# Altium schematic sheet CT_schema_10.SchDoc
size 405 x 220 mm
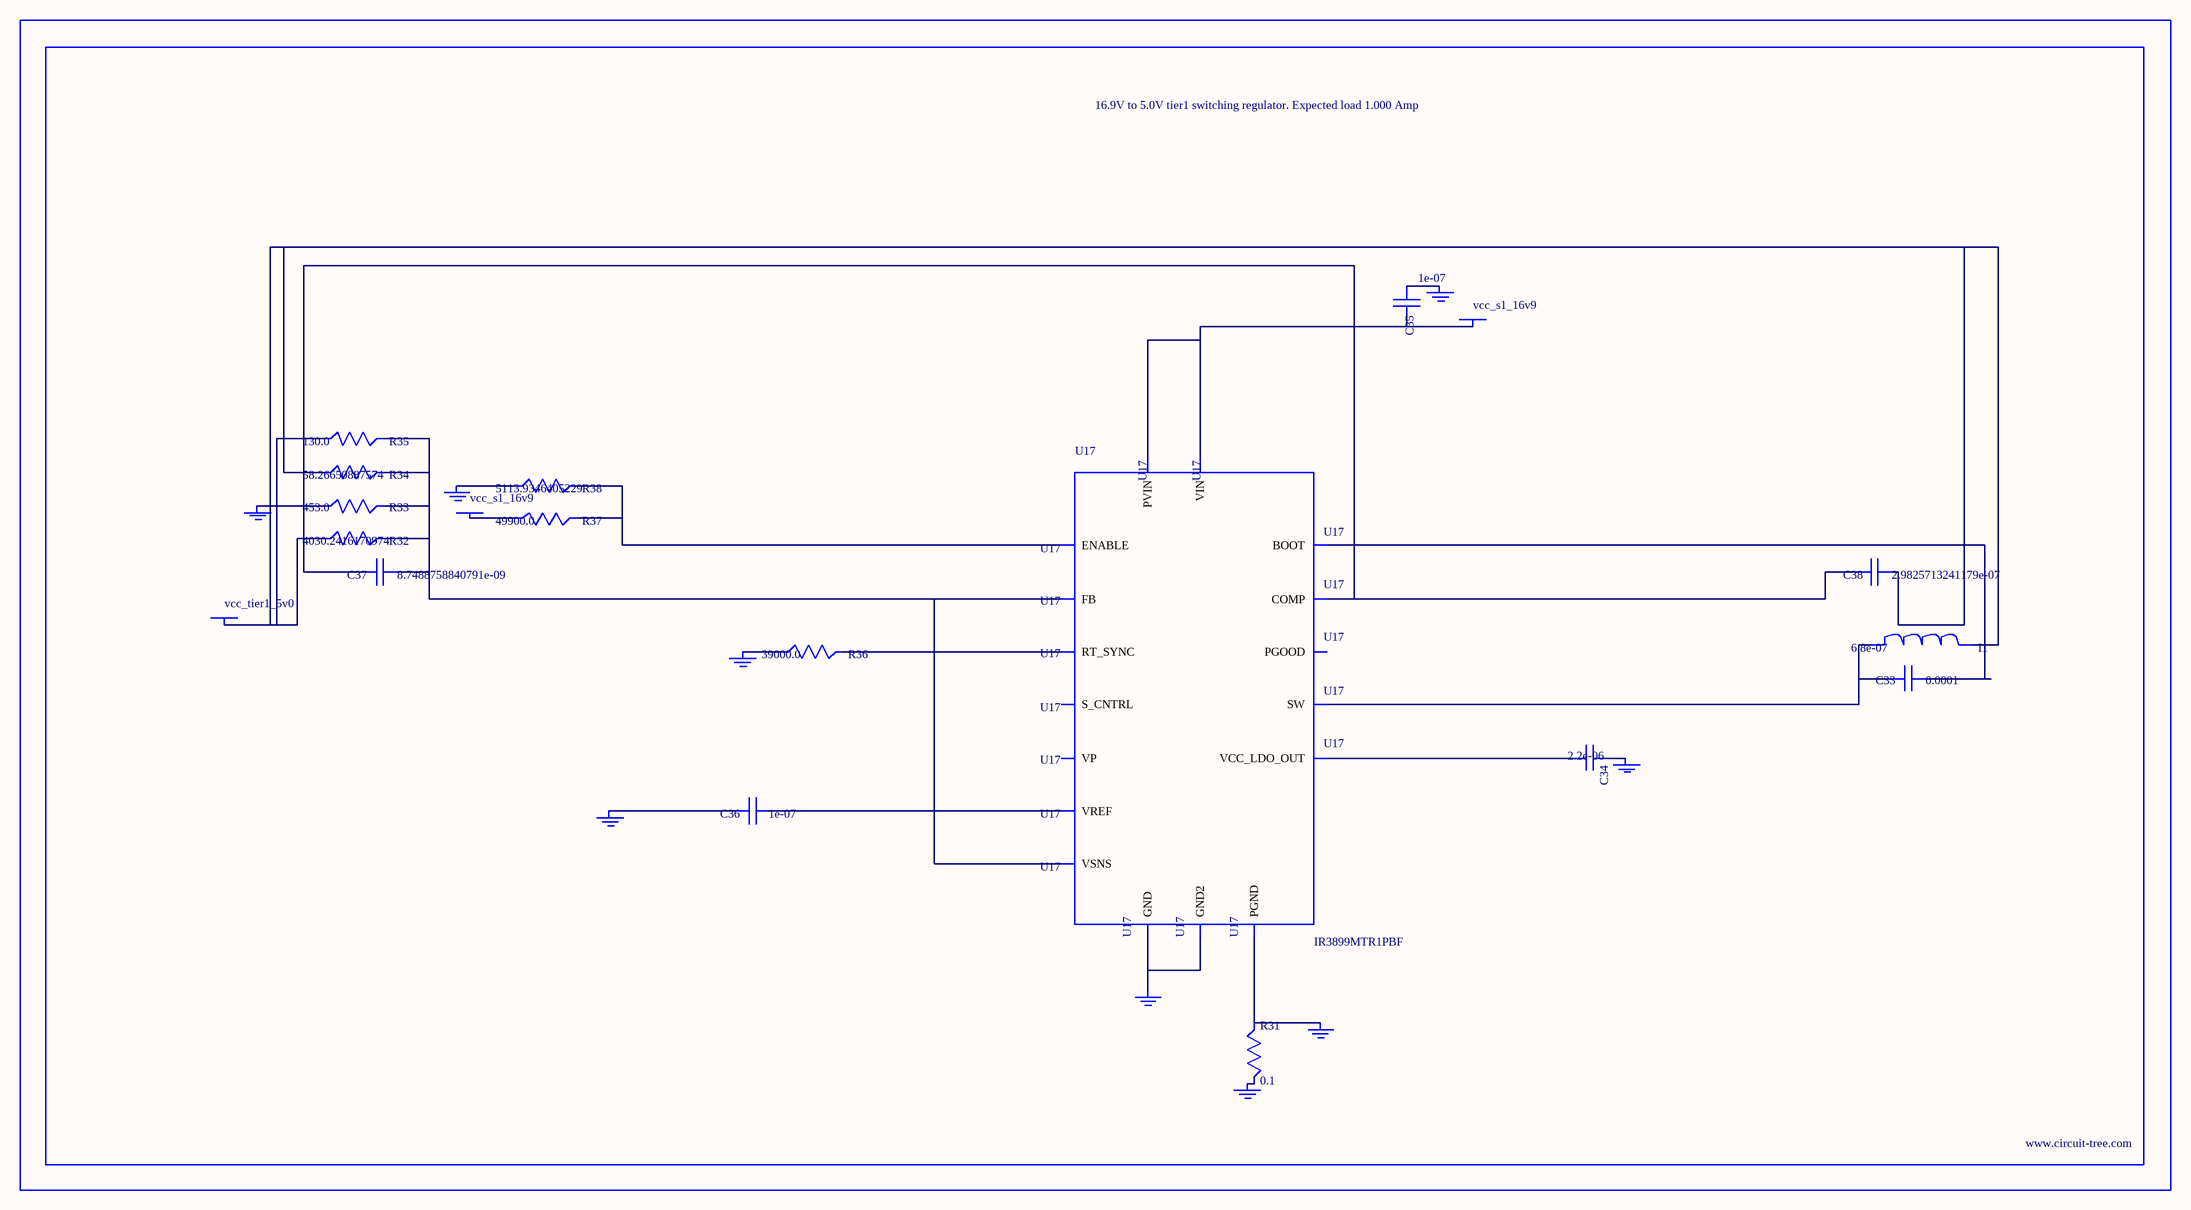
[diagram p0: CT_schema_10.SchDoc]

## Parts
BORDER9  (no value)
C33  0.0001  [C1210]
C34  2.2e-06  [C0603]
C35  1e-07  [C0402]
C36  1e-07  [C0402]
C37  8.7488758840791e-09  [R0603]
C38  2.9825713241179e-07  [R0603]
GND_INSTANCE_9_0  (no value)
GND_INSTANCE_9_1  (no value)
GND_INSTANCE_9_2  (no value)
GND_INSTANCE_9_3  (no value)
GND_INSTANCE_9_4  (no value)
GND_INSTANCE_9_5  (no value)
GND_INSTANCE_9_6  (no value)
GND_INSTANCE_9_7  (no value)
GND_INSTANCE_9_8  (no value)
I1  6.8e-07  [IND25X25CZ]
POWER_INSTANCE_9_0  vcc_s1_16v9
POWER_INSTANCE_9_1  vcc_s1_16v9
POWER_INSTANCE_9_2  vcc_tier1_5v0
R31  0.1  [R0603]
R32  4030.2416170974  [R0603]
R33  453.0  [R0603]
R34  58.26650887574  [R0603]
R35  130.0  [R0603]
R36  39000.0  [R0603]
R37  49900.0  [R0603]
R38  5113.9346405229  [R0603]
U17  IR3899MTR1PBF  [IR3899MTR1PBF]

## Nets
NetC33_1: C33.1 U17.14(BOOT)
NetC33_2: C33.2 I1.1 U17.12(SW)
NetC34_1: C34.1 GND_INSTANCE_9_4.0(GND)
NetC34_2: C34.2 U17.10(VCC_LDO_OUT)
NetC35_1: C35.1 GND_INSTANCE_9_3.0(GND)
NetC35_2: C35.2 POWER_INSTANCE_9_0.0(PWR) U17.9(VIN) U17.13(PVIN)
NetC36_1: C36.1 U17.2(VREF)
NetC36_2: C36.2 GND_INSTANCE_9_1.0(GND)
NetC37_1: C37.1 R32.2 R33.2 R34.2 R35.2 U17.1(FB) U17.8(VSNS)
NetC37_2: C37.2 C38.2 U17.3(COMP)
NetC38_1: C38.1 I1.2 POWER_INSTANCE_9_2.0(PWR) R32.1 R34.1 R35.1
NetGND_INSTANCE_9_0_0: GND_INSTANCE_9_0.0(GND) R33.1
NetGND_INSTANCE_9_2_0: GND_INSTANCE_9_2.0(GND) R36.1
NetGND_INSTANCE_9_5_0: GND_INSTANCE_9_5.0(GND) R31.2
NetGND_INSTANCE_9_6_0: GND_INSTANCE_9_6.0(GND) R31.1 U17.11(PGND)
NetGND_INSTANCE_9_7_0: GND_INSTANCE_9_7.0(GND) R38.1
NetGND_INSTANCE_9_8_0: GND_INSTANCE_9_8.0(GND) U17.4(GND) U17.17(GND2)
NetPOWER_INSTANCE_9_1_0: POWER_INSTANCE_9_1.0(PWR) R37.1
NetR36_2: R36.2 U17.5(RT_SYNC)
NetR37_2: R37.2 R38.2 U17.15(ENABLE)

Not connected (* = marked no-connect by the designer): U17 6(S_CNTRL) 7(PGOOD) 16(VP)

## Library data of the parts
BORDER9 = BORDER_PAGE9
C33 = GRM32ER61A107ME20L
C34 = C0603C225K8RACTU
C35 C36 = C0402C104K3RACTU
C37 = C37
C38 = C38
GND_INSTANCE_9_0-GND_INSTANCE_9_8 = GND
I1 = IHLP2525CZERR68M01
POWER_INSTANCE_9_0-POWER_INSTANCE_9_2 = PWR
R31 = ERJ-3RSFR10V
R32 = R32
R33 = ERJ-3EKF4530V
R34 = R34
R35 = RC0603JR-07130RL
R36 = RC0603JR-0739KL
R37 = RC0603FR-0749K9
R38 = R38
